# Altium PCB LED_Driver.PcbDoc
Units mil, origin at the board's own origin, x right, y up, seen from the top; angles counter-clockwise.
Board outline 665 x 975 mil, 2 copper layers (Top Layer, Bottom Layer); 23 components, 16 nets, 59 pads, 56 vias.
Unrouted connection lines stored in the file: 2.
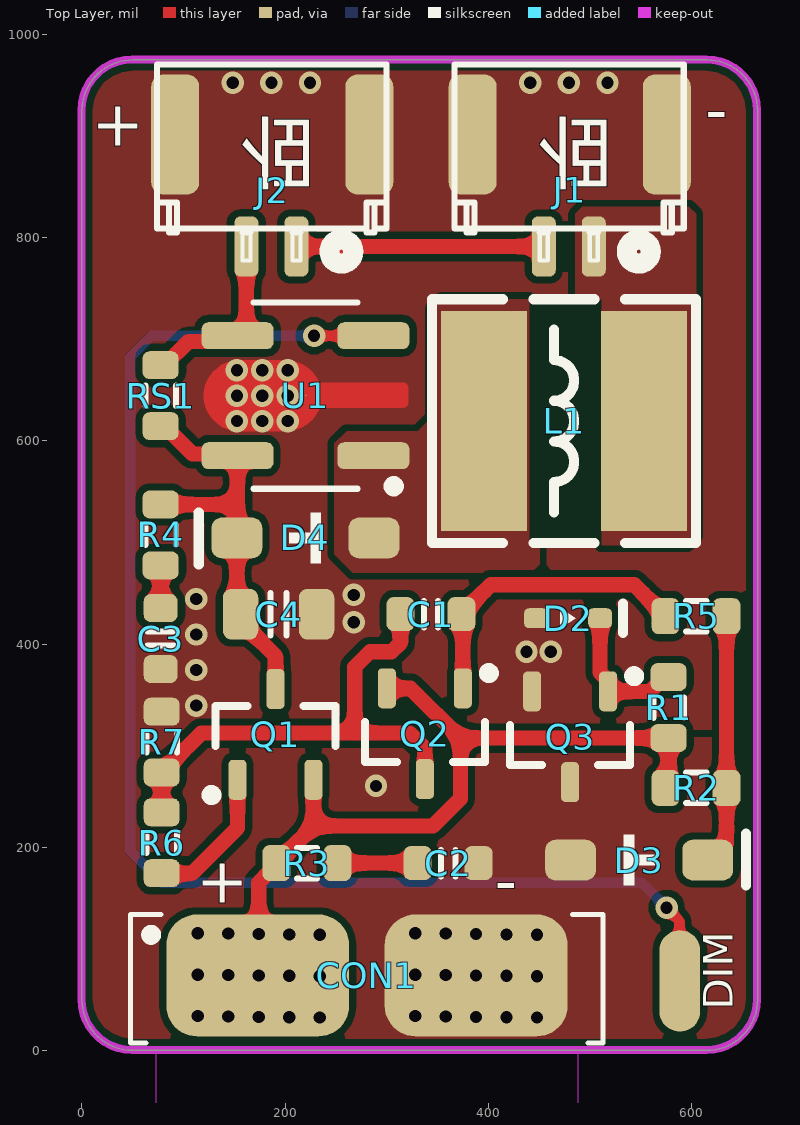
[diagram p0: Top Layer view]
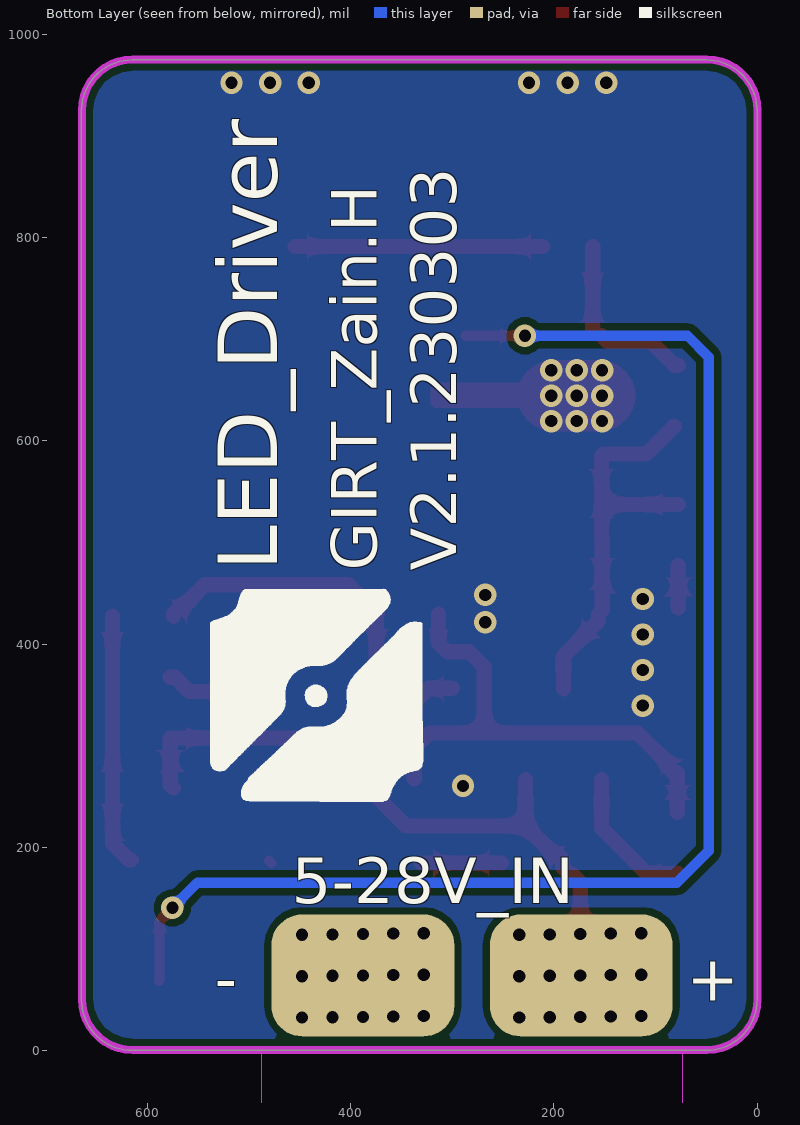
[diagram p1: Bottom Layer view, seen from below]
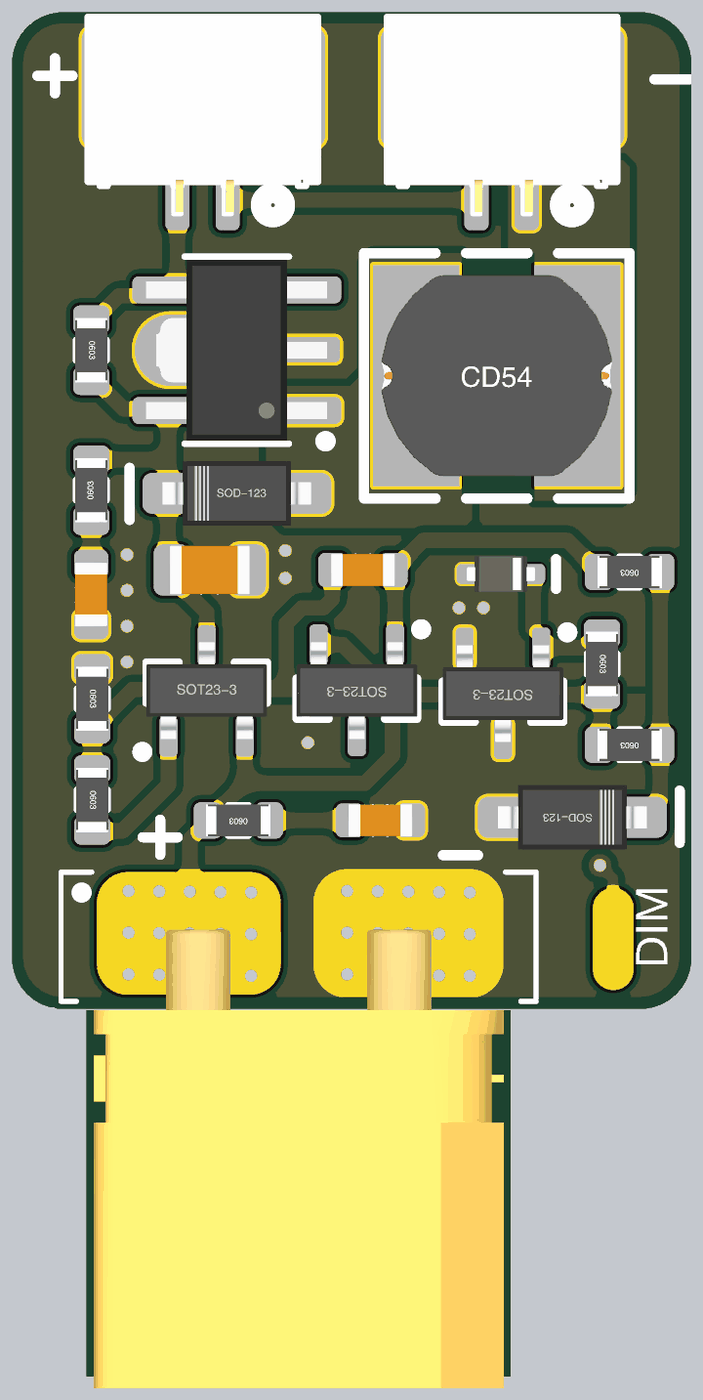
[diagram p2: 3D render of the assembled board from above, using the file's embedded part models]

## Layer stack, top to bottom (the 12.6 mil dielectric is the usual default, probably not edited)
Top Solder: solder mask 0.4, Solder Resist, Dk 3.5
Top Layer: signal copper 1.4
Dielectric 1: dielectric 12.6, FR-4, Dk 4.8
Bottom Layer: signal copper 1.4
Bottom Solder: solder mask 0.4, Solder Resist, Dk 3.5

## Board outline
0,50 ccw(c50,50) 50,0 615,0 ccw(c615,50) 665,50 665,925 ccw(c615,925) 615,975 50,975 ccw(c50,925) 0,925

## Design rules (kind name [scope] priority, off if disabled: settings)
AssemblyTestpoint AssemblyTestpoint_2 [All] p2: testpointundercomponent=TRUE minsize=40 maxsize=100 preferedsize=60 minholesize=0 maxholesize=40 preferedholesize=32 testpointgrid=1 usegrid=TRUE gridtolerance=0.01 allowsidetop=TRUE allowsidebottom=TRUE
AssemblyTestpoint AssemblyTestpoint_1 [All] p3: testpointundercomponent=TRUE minsize=40 maxsize=100 preferedsize=60 minholesize=0 maxholesize=40 preferedholesize=32 testpointgrid=1 usegrid=TRUE gridtolerance=0.01 allowsidetop=TRUE allowsidebottom=TRUE
Clearance [All] p1: gap=7 ignorepadtopadclearanceinfootprint=FALSE except(0: Arc-Hole Track-Hole SMDPad-Hole THPad-Hole Via-Hole Fill-Hole Poly-Hole Region-Hole Text-Hole)
ComponentClearance [All] p1: gap=0 collisioncheckmode=3 verticalgap=0 showdistances=FALSE
DiffPairsRouting [All] p1: maxlimit=100 minlimit=6 mostfreqgap=6 toplayer_minwidth=6 toplayer_maxwidth=100 toplayer_prefwidth=6 bottomlayer_minwidth=6 bottomlayer_maxwidth=100 bottomlayer_prefwidth=6 maxuncoupledlength=500
FanoutControl Fanout_BGA [All] p1: bgadir=Out bgaviamode=Centered fanoutstyle=Auto fanoutdirection=Alternating viagrid=1 // Fanout_BGA (Default Rule)
HoleSize [All] p1: absolutevalues=TRUE maxlimit=10000 minlimit=8 maxpercent=80.000 minpercent=20.000
MinimumSolderMaskSliver [All] p1 off: minsoldermaskwidth=2
PlaneClearance [All] p1: clearance=8
PlaneConnect [All] p1: planeconnectstyle=Direct reliefexpansion=20 reliefentries=4 reliefconductorwidth=10 reliefairgap=10
PolygonConnect [All] p1: connectstyle=Direct reliefconductorwidth=10 reliefentries=4 polygonreliefangle="90 Angle" airgapwidth=10
RoutingVias [All] p1: holewidth=8 width=16 viastyle="Through Hole" minholewidth=6 minwidth=12 maxholewidth=28 maxwidth=50
SilkToSilkClearance [All] p1: silktosilkclearance=0
SilkToSolderMaskClearance [IsPad] p1: minsilkscreentomaskgap=0 clearancetoexposedcopper=TRUE
SolderMaskExpansion [All] p1: expansion=3 istentingtop=FALSE
Width [All] p1: maxlimit=100 minlimit=6 preferedwidth=10
21 further rules are at their usual default settings.

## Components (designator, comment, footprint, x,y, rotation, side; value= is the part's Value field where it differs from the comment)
C1 "CL10B104KB8NNNC" "C 0603(1608)100_L" 343.5,429.42 r0 top value=100nF
C2 "CL10B103KB8NNNC" "C 0603(1608)100_L" 360.5,184.42 r180 top value=10nF
C3 "CL10B103KB8NNNC" "C 0603(1608)100_L" 77.5,405.42 r90 top value=10nF
C4 "CL21A475KBQNNNE" "C 0805(2012)_L" 193.5,429.42 r180 top value=4.7µF
CON1 "XT30UPB-M" XT30UPB-M-内嵌（翻转） 282.5,-85.58 r180 top
D2 "BZX584C9V1-V-G-08" SOD-523 478.5,425.42 r0 top
D3 "MMSZ5255BT1G" SOD-123 548.5,187.42 r0 top
D4 "B5819W" SOD-123 220,504.42 r180 top
J1 "LP1.25-SMD-2P" GH1.25-WS-2P 480.09,846.42 r0 top
J2 "LP1.25-SMD-2P" GH1.25-WS-2P 187.33,846.42 r0 top
L1 "CD54NP-101KC" CD54 474.5,619.42 r0 top value=100µH
Q1 "SI2319CDS-T1-GE3" SOT23-3L 190.5,311.42 r0 top
Q2 "PMBT3906,215" SOT23-3L 337.5,311.42 r180 top
Q3 "NCE6003" SOT23-3L 480.5,308.42 r180 top
R1 "RC0603FR-07100KL" "R 0603(1608)_L" 577.5,337.42 r270 top value=100k
R2 "RC0603FR-07100KL" "R 0603(1608)_L" 604.5,258.42 r180 top value=100k
R3 "RC0603FR-0733RL" "R 0603(1608)_L" 221.5,184.42 r180 top value=33
R4 "RC0603FR-0733RL" "R 0603(1608)_L" 77.5,507.42 r90 top value=33
R5 "RC0603FR-071KL" "R 0603(1608)_L" 604.5,427.42 r180 top value=1k
R6 "RC0603FR-071KL" "R 0603(1608)_L" 78.5,204.42 r270 top value=1k
R7 "RC0603FR-0710KL" "R 0603(1608)_L" 78.5,303.41 r270 top value=10k
RS1 "0603WAF820LT5E" "R 0603(1608)_L" 77.5,644.42 r270 top value=0.82
U1 "PT4205" SOT89-5N 220,644.42 r0 top

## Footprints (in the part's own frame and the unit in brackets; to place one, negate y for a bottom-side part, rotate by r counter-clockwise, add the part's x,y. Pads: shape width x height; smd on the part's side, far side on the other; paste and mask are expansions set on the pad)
"C 0603(1608)100_L" [mm] "长度1.6mm，宽度为0.8mm，高度0.8mm"
  rrect50% 0.7x0.849 smd: 1(-0.762,0) 2(0.762,0)
  silkscreen extent -0.18,-0.33 0.18,0.33, body extent -0.8,-0.41 0.8,0.41, height 0.81
"C 0805(2012)_L" [mil]
  rrect50% 35x50 smd: 1(-37.4,0) 2(37.4,0)
  silkscreen extent -8,-21 8,21, body extent -39,-24 39,24, height 20
CD54 [mm] "5.8*5.2*4.5mm（长宽高）"
  rect 2.15x5.5 smd: 1(-2,0) 2(2,0)
  silkscreen extent -3.3,-3.05 3.3,3.05, body extent -2.87,-2.5 2.87,2.5, height 4
GH1.25-WS-2P [mm]
  rrect50% 0.6x1.5 smd: 1(0.602,-1.4) 2(-0.648,-1.4)
  rrect50% 1.2x3 smd: 3(-2.426,1.4) 4(2.427,1.4)
  silkscreen extent -2.88,-1.83 2.85,3.15, body extent -2.84,-1.69 2.91,3.16, height 4.25
"R 0603(1608)_L" [mm]
  rrect50% 0.7x0.9 smd: 1(-0.762,0) 2(0.762,0)
  silkscreen extent -0.25,-0.38 0.25,0.38, body extent -0.8,-0.4 0.8,0.4, height 0.4
SOD-123 [mil] "2.7x1.6X1.1mm（长宽高，不包括引脚）"
  rrect50% 50x40 smd: 1(-67.5,0) 2(67.5,0)
  silkscreen extent -15,-25 105,26, body extent -73,-31 73,31, height 48
SOD-523 [mm] "ESC_L1.2-W0.8-LS1.6-RD"
  rrect50% 0.6x0.5 smd mask+0.051: 1(-0.8,0) 2(0.8,0)
  silkscreen extent -0.19,-0.37 1.37,0.37, body extent -0.85,-0.45 0.85,0.45, height 0.76
SOT23-3L [mm] "3x1.3x1mm(长宽高)"
  rrect50% 0.45x1 smd: 1(-0.95,-1.143) 2(0.95,-1.143) 3(0,1.125)
  silkscreen extent -1.72,-1.65 1.5,0.7, body extent -1.5,-1.2 1.5,1.2, height 1.05
SOT89-5N [mm]
  rrect50% 1.8x0.674 smd: 1(1.698,-1.5) 3(1.698,1.5) 4(-1.698,1.5) 5(-1.698,-1.5)
  round 0.025 smd: 2(0.013,0)
  Top Layer region: -1.651,-0.889 -2.037,-0.801 -2.346,-0.554 -2.518,-0.198 -2.518,0.198 -2.346,0.554 -2.037,0.801 -1.651,0.889 -1.651,0.889 -0.483,0.889 -0.14,0.82 0.15,0.625 0.342,0.333 0.342,0.333 0.356,0.33 2.438,0.33 2.487,0.321 2.528,0.293 2.556,0.252 2.565,0.203 2.565,0.203 2.565,-0.178 2.556,-0.226 2.528,-0.268 2.487,-0.295 2.438,-0.305 2.438,-0.305 0.356,-0.305 0.342,-0.333 0.15,-0.625 -0.14,-0.82 -0.483,-0.889 -0.483,-0.889
  silkscreen extent -1.3,-2.39 2.33,2.33, body extent -2.25,-2.25 2.25,2.25, height 1.54
XT30UPB-M-内嵌（翻转） [mil]
  rrect50% 180x120 smd paste-99999: A(109.5,-159.42) C(-105.5,-159.42)
  Keep-Out Layer board cut-out: 209.5,-84.42 -205.5,-84.42 -205.5,274.01 209.5,274.01
  silkscreen extent -230,-219 235,-93, body extent -199,-163 203,286, height 150

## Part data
C1: library part CMP-001-00085-4, "Multi Layer Ceramic Capacitor (MLCC) / Cap Ceramic 0.1uF 50V X7R 10% Pad SMD 0603 125¡ãC T/R", Capacitance=100nF, Case Code (Imperial)=0603, Case Code (Metric)=1608, Dielectric=X7R, Max Operating Temperature=125°C, Min Operating Temperature=-55°C, Package Quantity=1, Tolerance=10%, Voltage=50V
C2 C3: library part CMP-001-00105-3, "CAP CER 10000PF 50V X7R 0603", Case Code (Imperial)=0603, Case Code (Metric)=1608, Dielectric=X7R, Max Operating Temperature=125°C, Min Operating Temperature=-55°C, Package Quantity=1, Tolerance=10%, Voltage=50V
C4: library part CMP-001-00100-4, "CAP CER 4.7UF 50V X5R 0805", Case Code (Imperial)=0805, Case Code (Metric)=2012, Dielectric=X5R, Max Operating Temperature=85°C, Min Operating Temperature=-55°C, Package Quantity=1, Tolerance=10%, Voltage Rating=50V
CON1: library part CMP-002-00073-11, "12.7x10.2mm 铜镀金 DC500V 15A", Max Current Rating=15A, Max Operating Temperature=120°C, Min Operating Temperature=-20°C, Momentary Current=30A, Voltage Rating=500V
D2: library part CMP-004-00055-5, "Diode Zener Single 9.1V 5% 200mW 2-Pin SOD-523 T/R", Max Operating Temperature=150°C, Max Power Dissipation=200mW, Max Reverse Leakage Current=500nA, Min Operating Temperature=-65°C, Test Current=5mA, Tolerance=5%, Zener Voltage=9.1V
D3: library part CMP-004-00057-2, "MMSZ5255BT1 Series 500 mW 10 mA 28 V SMT Zener Voltage Regulator - SOD-123", Case/Package=SOD-123-2, Forward Voltage=900mV, Max Operating Temperature=150°C, Max Power Dissipation=500mW, Max Reverse Current=100nA, Min Operating Temperature=-55°C, Package Quantity=3000, Test Current=4.5mA, Tolerance=5%, Voltage Rating (DC)=28V, Zener Current=10mA
D4: library part CMP-004-00044-11, "DIODE SCHOTTKY 20V 1A SOD123", Average Rectified Current=1A, Case/Package=SOD123, Forward Voltage=550mV, Max Forward Surge Current (Ifsm)=10A, Max Operating Temperature=125°C, Max Power Dissipation=250mW, Max Repetitive Reverse Voltage (Vrrm)=40V, Max Reverse Current=1mA, Max Reverse Voltage (DC)=20V, Min Operating Temperature=-65°C, Package Description="2-Pin Small Outline Diode, Body 2.7 x 1.6 mm, Height 1.35 mm", Package Quantity=3000
J1 J2: library part CMP-002-00326-2, "脚距1.25，表面贴装，2pin接插件"
L1: library part CMP-006-00038-2, "Ind Power Unshielded Wirewound 100uH 10% 1KHz 520mA Carrier T/R", Case/Package=Nonstandard, Current Rating=520mA, DC Resistance (DCR)=700mR, Max Operating Temperature=100°C, Min Operating Temperature=-40°C, Package Quantity=1500, Test Frequency=1kHz, Tolerance=10%
Q1: library part CMP-013-00039-5, "MOSFET P-CH 40V 4.4A SOT-23", Case/Package=SOT-23, Continuous Drain Current (ID)=-4.4A, Drain to Source Breakdown Voltage=-40V, Drain to Source Resistance=64mR, Drain-source On Resistance-Max=77mR, Gate to Source Voltage (Vgs)=20V, Input Capacitance=595pF, Max Operating Temperature=150°C, Max Power Dissipation=2.5W, Min Operating Temperature=-55°C, Package Quantity=1, Power Dissipation=1.25W, Threshold Voltage=-1.2V
Q2: library part CMP-013-00040-2, "PNP Ic=-200mA Vceo=-40V hfe=100~300 fT=250MHz P=250mW", Power=250mW
Q3: library part MOS-00001-2, "60V 3A 1.7W 105m´Î@10V3A 2V@250Ã×A N Channel SOT-23(SOT-23-3) MOSFETs ROHS"
R1 R2: library part CMP-007-00090-4, "RES SMD 100K OHM 1% 1/10W 0603", Case Code (Imperial)=0603, Case Code (Metric)=1608, Max Operating Temperature=155°C, Max Power Dissipation=100mW, Min Operating Temperature=-55°C, Resistance Tolerance=1%, Resistor Type="Thick Film", Temperature Coefficient=100ppm/°C, Voltage Rating=50V, Working Voltage=75V
R3 R4: library part CMP-009-00202-4, "Res Thick Film 0603 33 Ohm 1% 1/10W +/-100ppm/ßC Molded SMD Paper T/R", Case Code (Imperial)=0603, Case Code (Metric)=1608, Max Operating Temperature=155°C, Max Power Dissipation=100mW, Min Operating Temperature=-55°C, Package Quantity=1, Resistance Tolerance=1%, Resistor Type="Thick Film", Temperature Coefficient=100ppm/°C, Voltage Rating=75V, Voltage Rating (DC)=50V
R5 R6: library part CMP-009-00199-4, "Res Thick Film 0603 1K Ohm 1% 1/10W ±100ppm/°C Molded SMD SMD Paper T/R", Case Code (Imperial)=0603, Case Code (Metric)=1608, Max Operating Temperature=155°C, Max Power Dissipation=100mW, Min Operating Temperature=-55°C, Resistance Tolerance=1%, Resistor Type="Thick Film", Temperature Coefficient=100ppm/°C, Voltage Rating=50V
R7: library part CMP-009-00017-13, "RES SMD 10K OHM 1% 1/10W 0603", Case Code (Imperial)=0603, Case Code (Metric)=1608, Max Operating Temperature=155°C, Max Power Dissipation=100mW, Min Operating Temperature=-55°C, Resistance Tolerance=1%, Resistor Type="Thick Film", Temperature Coefficient=100ppm/°C, Voltage Rating=75V, Voltage Rating (DC)=50V
RS1: library part CMP-007-00091-3, "贴片电阻 0.82Ω ± 1.00% 0.1W ± 800ppm/℃ 0603", Case/Package=0603, Power=100mW, Tolerance=1%
U1: library part CMP-019-00087-5, "30V/1.2A/高调光比 LED 恒流驱动器"

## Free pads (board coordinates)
  oval 40x100 smd paste-99999: 2(588.5,68.42)
  rrect50% 180x120 smd far side paste-99999: 3(173,73.83) 3(388,73.83)

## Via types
v1: diameter 22, hole 12, Top Layer to Bottom Layer, 30 vias
v2: diameter 22, hole 12, Top Layer to Bottom Layer, tented both sides, 26 vias

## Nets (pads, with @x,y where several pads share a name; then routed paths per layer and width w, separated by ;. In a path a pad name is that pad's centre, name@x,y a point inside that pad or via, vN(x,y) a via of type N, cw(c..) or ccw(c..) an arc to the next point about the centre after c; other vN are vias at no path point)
DIM: pad.2 U1.3 | length 1362.6
  Top Layer w10: v2(228.5,703.42) 286.78,703.42 U1.3 ; v2(575.5,140.42) 575.5,140.2 588.14,127.56 588.14,68.77 pad.2
  Bottom Layer w10: v2(228.5,703.42) 68.5,703.42 47.5,682.42 47.5,196.5 79,165 550.92,165 v2(575.5,140.42)
GND: C3.1 C4.1 D2.1 J1.3 J1.4 J2.3 J2.4 Q3.2 R7.1 U1.2
  other v2: 289.5,260.42 112.5,339.42 112.5,374.42 437.5,392.42 461.5,392.42 112.5,409.42 267.5,421.42 112.5,444.42 267.5,448.42 152.5,619.42 177.5,619.42 202.5,619.42 152.5,644.42 177.5,644.42 202.5,644.42 152.5,669.42 177.5,669.42 202.5,669.42 148.5,952.42 186.5,952.42 224.5,952.42 441.26,952.42 479.26,952.42 517.26,952.42
GND_BAT: C2.1 CON1.C D3.1 pad.3@388,73.83 Q3.3 | length 3.5
  Top Layer w10: D3.1@478,184.42 D3.1@480.5,186.92
  other v1: 418,32.67 448,32.29 328,33.8 358,33.42 388,33.05 388,73.83 418,73.46 448,73.08 328,74.59 358,74.21 448,113.87 388,114.62 418,114.25 328,115.38 358,115
LED+: J2.2 RS1.1 U1.4 | length 169.8
  Top Layer w15: RS1.1 81.44,674.42 104.72,697.7 147.4,697.7 U1.4 ; U1.4@161.8,709.24 J2.2
LED−: J1.1 L1.2
NetC1_1: C1.1 Q2.3 R6.1 R7.2 | length 501
  Top Layer w15: R6.1 R7.2 82.44,273.42 88.72,279.7 88.72,283.63 117.5,312.42 268.5,312.42 ; C1.1 313.44,429.35 313.44,401.2 304.65,392.42 283.57,392.42 268.5,377.34 268.5,312.42 ; Q2.3 337.5,297.42 322.5,312.42 268.5,312.42
NetC1_2: C1.2 Q2.1 R5.2 | length 302.3
  Top Layer w15: Q2.1 374.9,428.01 C1.2 373.5,431.33 382.13,439.97 384.05,439.97 402.5,458.42 543.51,458.42 562.96,438.97 565.87,438.97 574.51,430.33 R5.2
NetC2_2: C2.2 R3.1 | length 79
  Top Layer w15: R3.1 C2.2
NetC3_2: C3.2 R4.1 | length 42
  Top Layer w15: C3.2 R4.1
NetD2_2: D2.2 Q3.1 R1.1 | length 140.7
  Top Layer w15: D2.2 510,372.15 517.9,364.24 Q3.1 558.93,353.42 572.93,367.42 R1.1
NetD3_2: D3.2 R2.1 R5.1 | length 249
  Top Layer w15: D3.2 618.29,187.42 634.5,203.62 R2.1 R5.1
NetD4_1: D4.1 L1.1 U1.1
NetJ1_2: J1.2 J2.1 | length 243.6
  Top Layer w15: J2.1 J1.2
NetQ1_1: Q1.1 R6.2 | length 140.8
  Top Layer w15: R6.2 78.86,174.06 108.14,174.06 153.1,219.02 Q1.1
VCC_24V: C4.2 D4.2 Q1.3 R4.2 RS1.2 U1.5 | length 405.1
  Top Layer w15: R4.2 153.16,537.41 ; RS1.2@81.44,614.42 108.77,587.09 151.44,587.09 U1.5 153.17,537.42 ; Q1.3 190.5,388.2 156.1,422.6 C4.2 152.5,433.02 D4.2 153.17,505.09 153.17,537.42
VCC_BAT: CON1.A pad.3@173,73.83 Q1.2 Q2.2 R1.2 R2.2 R3.2 | length 782
  Top Layer w15: v1(174,73.83) v1(174,114.62) 174,165.41 182.79,174.2 185.23,174.2 191.51,180.48 R3.2 191.51,188.35 197.79,194.63 201.72,194.63 227.9,220.81 ; Q1.2 227.9,220.81 ; Q2.2 323.5,356.42 372.49,307.42 ; R2.2 577.5,261.41 R1.2 372.49,307.42 ; 227.9,220.81 345.5,220.81 372.49,247.81 372.49,307.42
  other v1: 204,32.67 234,32.29 114,33.8 144,33.42 174,33.05 204,73.46 234,73.08 114,74.59 144,74.21 234,113.87 204,114.25 114,115.38 144,115

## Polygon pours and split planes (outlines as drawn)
GND on Bottom Layer "NONET_L01_P-001" (solid, remove dead copper, pour order 18): 0,50 0,925 cw(c50,925) 50,975 615,975 cw(c615,925) 665,925 665,50 cw(c615,50) 615,0 50,0 cw(c50,50)
GND on Top Layer "NONET_L01_P-001" (solid, remove dead copper, pour order 17): 0,50 0,925 cw(c50,925) 50,975 615,975 cw(c615,925) 665,925 665,50 cw(c615,50) 615,0 50,0 cw(c50,50)
GND_BAT on Top Layer "NONET_L01_P-001" (solid, remove dead copper, pour order 16): 174.5,-1.58 174.5,308.42 664.5,308.42 664.5,-0.58
LED− on Top Layer "NONET_L01_P-001" (solid, remove dead copper, pour order 14): 499.5,727.42 485.5,741.42 485.5,823.42 492.5,830.42 597.5,830.42 604.5,823.42 604.5,506.42 595.5,497.42 511.5,497.42 499.5,509.42
NetD4_1 on Top Layer "NONET_L01_P-001" (solid, remove dead copper, pour order 13): 248.5,597.42 260.5,609.42 330.5,609.42 344.5,623.42 344.5,730.42 353.5,739.42 440.5,739.42 450.5,729.42 450.5,478.42 442.5,470.42 266.5,470.42 248.5,488.42

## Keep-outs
Keep-Out Layer:
  lines w8: -0.5,50.42 ccw(c49.5,50.42) 49.5,0.42 614.5,0.42 ccw(c614.5,50.42) 664.5,50.42 664.5,925.42 ccw(c614.5,925.42) 614.5,975.42 579.5,975.42 49.5,975.42 ccw(c49.5,925.42) -0.5,925.42 -0.5,50.42

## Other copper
Top Layer:
  pour cut-out: 440.5,739.42 511.5,739.42 511.5,497.42 440.5,497.42

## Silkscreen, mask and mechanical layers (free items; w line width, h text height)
Top Overlay:
  text "-" at 613.5,904.42 h45
  text "+" at 9.5,890.42 h45
  text "+" at 112.5,145.42 h45
  text "-" at 406.5,145.42 h45
  text "DIM" at 650.51,39.82 h50 r90
Bottom Overlay:
  drawing of 3 lines, arcs and shapes, not listed
  text "V2.1.230303" at 296,472 h45 r270
  text "GIRT_Zain.H" at 374.5,472 h45 r270
  text "LED_Driver" at 453,472 h100 r270
  text "5-28V_IN" at 458,145 h45
  text "+" at 69,49 h45
  text "-" at 534,49 h45
Mechanical 1:
  lines w8: 0,50 ccw(c50,50) 50,0 615,0 ccw(c615,50) 665,50 665,925 ccw(c615,925) 615,975 580,975 50,975 ccw(c50,925) 0,925 0,50
Drill Drawing:
  circle w10: c99.62,1283.83 r33.33
  lines w15: 6.5,1205.5 10477.6,1205.5 ; 6.5,1355.5 10477.6,1355.5 ; 557.38,1055.5 557.38,1505.5 ; 1097.24,1055.5 1097.24,1505.5 ; 2186.92,1055.5 2186.92,1505.5 ; 2692.8,1055.5 2692.8,1505.5 ; 3426.6,1055.5 3426.6,1505.5 ; 4926.15,1055.5 4926.15,1505.5 ; 5516,1055.5 5516,1505.5 ; 6261.79,1055.5 6261.79,1505.5 ; 6911.62,1055.5 6911.62,1505.5 ; 7765.39,1055.5 7765.39,1505.5 ; 9098.99,1055.5 9098.99,1505.5 ; 6.5,1055.5 10477.6,1055.5 10477.6,1505.5 6.5,1505.5 6.5,1055.5
  text "Symbol" at 96.5,1400.5 h72
  text "Count" at 602.38,1400.5 h72
  text "Hole Size" at 1142.24,1400.5 h72
  text "Plated" at 2231.92,1400.5 h72
  text "Hole Type" at 2737.8,1400.5 h72
  text "Drill Layer Pair" at 3471.6,1400.5 h72
  text "Via/Pad" at 4971.15,1400.5 h72
  text "Pad Shape" at 5561,1400.5 h72
  text "Template" at 6306.79,1400.5 h72
  text "Description" at 6956.62,1400.5 h72
  text "Hole Tolerance (+)" at 7810.39,1400.5 h72
  text "Hole Tolerance (-)" at 9143.99,1400.5 h72
  text "56" at 602.38,1250.5 h60
  text "12.00mil (0.305mm)" at 1142.24,1250.5 h60
  text "PTH" at 2231.92,1250.5 h60
  text "Round" at 2737.8,1250.5 h60
  text "Top Layer - Bottom Layer" at 3471.6,1250.5 h60
  text "Via" at 4971.15,1250.5 h60
  text "Rounded" at 5561,1250.5 h60
  text "(Mixed)" at 6306.79,1250.5 h60
  text "56 Total" at 602.38,1100.5 h60

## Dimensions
0,50 to 665,50 on Mechanical 1
50,975 to 50,0 on Mechanical 1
